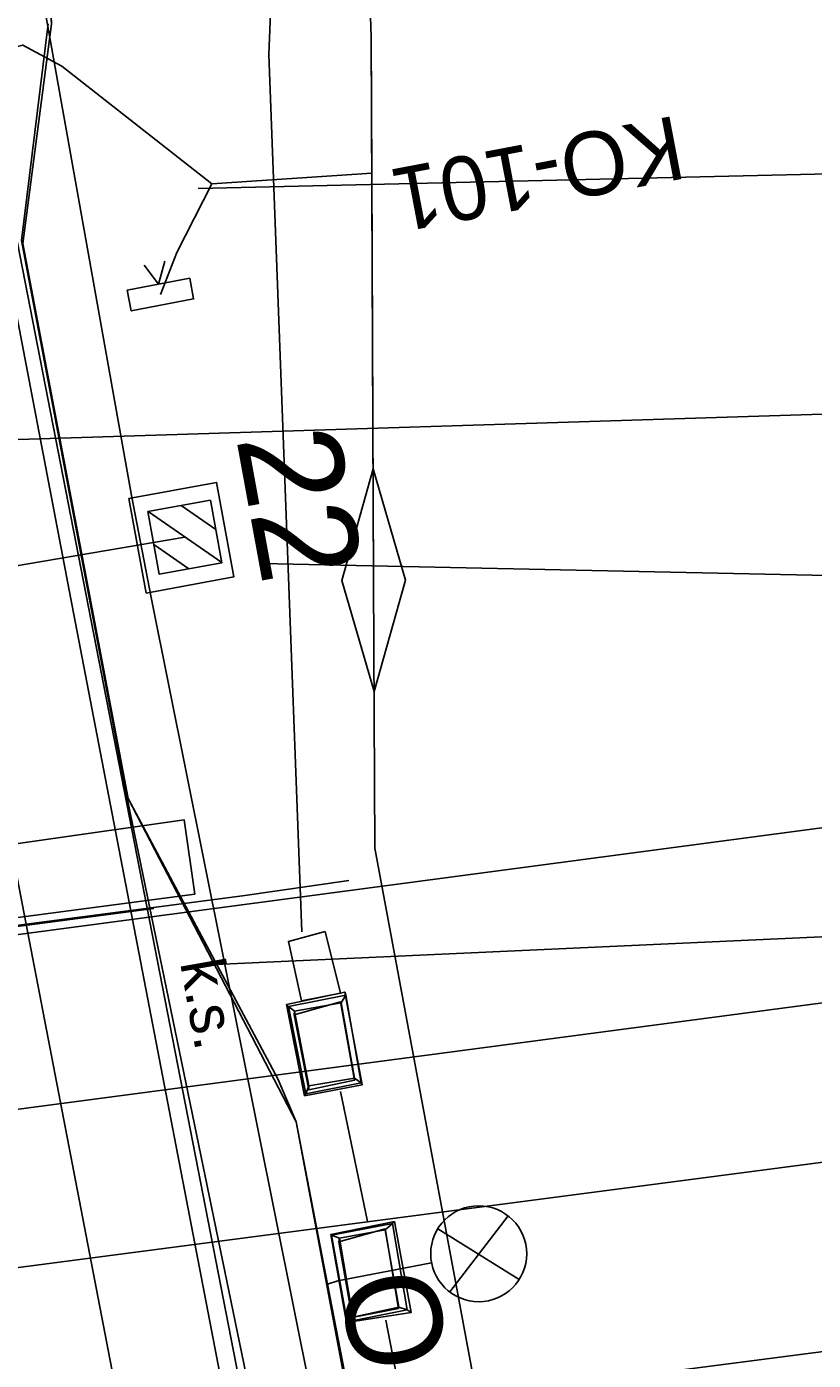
# Model space of a CAD drawing. Extents: x -545736 to -544888, y -1122892 to -1119128.
# Drawn here: x -545096.04 to -545083.68, y -1122320.45 to -1122299.49 of the extents above; entities that cross this region are included whole.
import ezdxf

# ---------------------------------------------------------------- set-up
doc = ezdxf.new("R2010")
doc.units = 0
for name, color, linetype in [('osvětlené plochy-hodnota-obrys', 7, 'Continuous'), ('Vrstva 1', 7, 'Continuous'), ('Vrstva 1 - Koleje', 7, 'Continuous'), ('Vrstva 11 - Trakce', 7, 'Continuous'), ('Vrstva 12 - Trakce zaklady', 7, 'Continuous'), ('Vrstva 17', 7, 'Continuous'), ('Vrstva 17_ploty - zabradli', 7, 'Continuous'), ('Vrstva 18', 7, 'Continuous'), ('Vrstva 25', 7, 'Continuous'), ('Vrstva 26', 7, 'Continuous'), ('Vrstva 27', 7, 'Continuous'), ('Vrstva 28 - zabzar', 7, 'Continuous'), ('Vrstva 31', 7, 'Continuous'), ('Vrstva 32', 7, 'Continuous'), ('Vrstva 36', 7, 'Continuous'), ('Vrstva 4 - Teren - stezky - prechody - plochy', 7, 'Continuous'), ('Vrstva 51', 7, 'Continuous'), ('Vrstva 63', 7, 'Continuous')]:
    doc.layers.add(name, color=color, linetype=linetype)

msp = doc.modelspace()

# ---------------------------------------------------------------- linework, layer by layer
at = {"layer": 'osvětlené plochy-hodnota-obrys'}
msp.add_lwpolyline([(-545104.447, -1122260.603), (-545047.997, -1122549.826)], dxfattribs=at)
at = {"layer": 'Vrstva 1'}
for points in [[(-545148.51, -1122325.585), (-545144.135, -1122325.279), (-545127.963, -1122323.132), (-545101.215, -1122319.654), (-545075.12, -1122316.237)], [(-545074.598, -1122319.154), (-545096.849, -1122322.043), (-545128.213, -1122326.198), (-545143.569, -1122328.203), (-545147.826, -1122328.702)]]:
    msp.add_lwpolyline(points, dxfattribs=at)
at = {"layer": 'Vrstva 1 - Koleje'}
msp.add_lwpolyline([(-545113.376, -1122218.519), (-545113.071, -1122220.278), (-545112.348, -1122224.453), (-545111.157, -1122231.266), (-545109.547, -1122240.396), (-545108.011, -1122249.024), (-545106.448, -1122257.717), (-545104.028, -1122271.035), (-545102.537, -1122279.147), (-545101.024, -1122287.292), (-545099.431, -1122295.796), (-545097.933, -1122303.72), (-545096.244, -1122312.592), (-545094.57, -1122321.295), (-545093.263, -1122328.028), (-545091.542, -1122336.847), (-545089.85, -1122345.509), (-545088.55, -1122352.199), (-545087.631, -1122356.921)], dxfattribs=at)
at = {"layer": 'Vrstva 11 - Trakce'}
for p, q in [((-545093.614, -1122307.016), (-545093.07, -1122307.391)), ((-545094.135, -1122307.112), (-545092.975, -1122307.913)), ((-545114.361, -1122311.03), (-545093.556, -1122307.514)), ((-545094.043, -1122307.631), (-545093.492, -1122308.011))]:
    msp.add_line(p, q, dxfattribs=at)
msp.add_lwpolyline([(-545093.154, -1122306.932), (-545092.974, -1122307.916), (-545093.958, -1122308.096), (-545094.138, -1122307.112)], close=True, dxfattribs=at)
at = {"layer": 'Vrstva 12 - Trakce zaklady'}
for p, q in [((-545094.436, -1122306.906), (-545093.059, -1122306.654)), ((-545092.787, -1122308.139), (-545094.164, -1122308.391))]:
    msp.add_line(p, q, dxfattribs=at)
for points in [[(-545094.164, -1122308.391), (-545094.436, -1122306.906), (-545093.059, -1122306.654), (-545092.787, -1122308.139), (-545094.164, -1122308.391)], [(-545093.059, -1122306.654), (-545093.059, -1122306.654), (-545092.787, -1122308.139), (-545092.787, -1122308.139)], [(-545094.436, -1122306.906), (-545094.436, -1122306.906), (-545094.164, -1122308.391), (-545094.164, -1122308.391)]]:
    msp.add_lwpolyline(points, dxfattribs=at)
at = {"layer": 'Vrstva 17'}
for p, q in [((-545090.684, -1122318.27), (-545091.11, -1122316.223)), ((-545090, -1122321.861), (-545090.398, -1122319.821))]:
    msp.add_line(p, q, dxfattribs=at)
for points in [[(-545091.717, -1122313.718), (-545092.238, -1122299.93), (-545089.495, -1122232.824), (-545090.394, -1122139.176), (-545080.236, -1122138.183), (-545080.486, -1122136.786), (-545077.607, -1122137.095), (-545077.582, -1122138.495)], [(-545150.29, -1122320.438), (-545144.887, -1122320.012), (-545115.504, -1122316.324), (-545074.789, -1122310.916)], [(-545074.698, -1122313.665), (-545111.863, -1122318.578), (-545144.692, -1122322.779), (-545149.67, -1122323.128)]]:
    msp.add_lwpolyline(points, dxfattribs=at)
msp.add_lwpolyline([(-545113.399, -1122315.705), (-545113.531, -1122314.631), (-545106.085, -1122313.699), (-545100.154, -1122312.892), (-545093.568, -1122311.954), (-545093.401, -1122313.123), (-545099.916, -1122313.983), (-545105.938, -1122314.779)], close=True, dxfattribs=at)
at = {"layer": 'Vrstva 17_ploty - zabradli'}
msp.add_line((-545111.225, -1122315.617), (-545094.046, -1122313.35), dxfattribs=at)
at = {"layer": 'Vrstva 18'}
for points in [[(-545145.417, -1122319.736), (-545144.484, -1122319.672), (-545119.425, -1122316.644), (-545117.758, -1122316.442), (-545092.653, -1122313.15), (-545090.978, -1122312.91)], [(-545091.043, -1122314.664), (-545091.024, -1122314.713), (-545091.099, -1122314.832), (-545091.112, -1122314.818)], [(-545091.958, -1122314.859), (-545091.929, -1122314.889), (-545091.833, -1122314.964), (-545091.838, -1122315.022)], [(-545090.771, -1122316.12), (-545090.787, -1122316.087), (-545090.888, -1122316.014), (-545090.889, -1122316.049)], [(-545091.677, -1122316.292), (-545091.657, -1122316.264), (-545091.606, -1122316.137), (-545091.608, -1122316.2)], [(-545090.264, -1122318.27), (-545090.295, -1122318.301), (-545090.409, -1122318.402), (-545090.408, -1122318.386)], [(-545091.264, -1122318.475), (-545091.251, -1122318.481), (-545091.126, -1122318.531), (-545091.138, -1122318.586)], [(-545090.002, -1122319.7), (-545090.063, -1122319.656), (-545090.195, -1122319.613), (-545090.199, -1122319.634)], [(-545091.016, -1122319.855), (-545091.004, -1122319.843), (-545090.917, -1122319.77), (-545090.927, -1122319.778)]]:
    msp.add_lwpolyline(points, dxfattribs=at)
for points in [[(-545091.677, -1122316.292), (-545090.771, -1122316.12), (-545091.043, -1122314.664), (-545091.958, -1122314.859)], [(-545091.657, -1122316.264), (-545090.787, -1122316.087), (-545091.024, -1122314.713), (-545091.929, -1122314.889)], [(-545091.838, -1122315.022), (-545091.608, -1122316.2), (-545090.889, -1122316.049), (-545091.112, -1122314.818)], [(-545091.606, -1122316.137), (-545090.888, -1122316.014), (-545091.099, -1122314.832), (-545091.833, -1122314.964)], [(-545091.016, -1122319.855), (-545090.002, -1122319.7), (-545090.264, -1122318.27), (-545091.264, -1122318.475)], [(-545091.004, -1122319.843), (-545090.063, -1122319.656), (-545090.295, -1122318.301), (-545091.251, -1122318.481)], [(-545090.927, -1122319.778), (-545090.199, -1122319.634), (-545090.408, -1122318.386), (-545091.138, -1122318.586)], [(-545090.917, -1122319.77), (-545090.195, -1122319.613), (-545090.409, -1122318.402), (-545091.126, -1122318.531)]]:
    msp.add_lwpolyline(points, close=True, dxfattribs=at)
at = {"layer": 'Vrstva 25'}
for p, q in [((-545088.477, -1122318.179), (-545089.394, -1122319.376)), ((-545088.301, -1122319.179), (-545089.583, -1122318.384)), ((-545089.679, -1122318.916), (-545091.152, -1122319.199))]:
    msp.add_line(p, q, dxfattribs=at)
msp.add_circle((-545088.938, -1122318.776), 0.754, dxfattribs=at)
at = {"layer": 'Vrstva 26'}
for points in [[(-545091.312, -1122319.256), (-545091.806, -1122316.702), (-545092.096, -1122316.024), (-545094.445, -1122311.621), (-545096.102, -1122302.896), (-545095.653, -1122299.445), (-545095.783, -1122296.662), (-545096.017, -1122293.637), (-545097.072, -1122285.85), (-545097.996, -1122280.011), (-545097.935, -1122279.662), (-545098.223, -1122276.93), (-545099.99, -1122270.495), (-545100.829, -1122263.058), (-545101.528, -1122261.609)], [(-545089.248, -1122329.984), (-545089.355, -1122329.595), (-545090.625, -1122323.213), (-545090.711, -1122322.359), (-545091.312, -1122319.256), (-545091.152, -1122319.199)]]:
    msp.add_lwpolyline(points, dxfattribs=at)
at = {"layer": 'Vrstva 27'}
msp.add_line((-545094.462, -1122303.633), (-545094.459, -1122303.629), dxfattribs=at)
msp.add_lwpolyline([(-545094.197, -1122303.24), (-545093.971, -1122303.536), (-545093.87, -1122303.178)], dxfattribs=at)
msp.add_lwpolyline([(-545094.462, -1122303.63), (-545093.48, -1122303.443), (-545093.418, -1122303.77), (-545094.4, -1122303.957)], close=True, dxfattribs=at)
at = {"layer": 'Vrstva 28 - zabzar'}
for points in [[(-545090.63, -1122299.65), (-545090.83, -1122293.64), (-545090.33, -1122285.9), (-545090.39, -1122281.43), (-545091.98, -1122278.11), (-545093.76, -1122273.59), (-545094.94, -1122269.52), (-545095.9, -1122261.38), (-545096.26, -1122251.32), (-545096.96, -1122243.55), (-545098.17, -1122239.69), (-545098.65, -1122230.66), (-545099.12, -1122222.68), (-545099.31, -1122222.23), (-545100.05, -1122215.99), (-545100.8, -1122212.68), (-545103.53, -1122204.35), (-545105.03, -1122196.24), (-545105.2, -1122196.04), (-545111.19, -1122191.9), (-545111.86, -1122183.52), (-545111.88, -1122183.3)], [(-545095.98, -1122406.73), (-545094.09, -1122406.23), (-545085.61, -1122404.88), (-545075.19, -1122403.13), (-545078.57, -1122384.82), (-545080.03, -1122378.7), (-545078.63, -1122376.44), (-545078.73, -1122374.54), (-545080.88, -1122364.73), (-545082.7, -1122354.07), (-545083.77, -1122348.32), (-545086.63, -1122333.57), (-545090.57, -1122312.4), (-545090.59, -1122308.19), (-545090.62, -1122301.79), (-545090.63, -1122299.65)], [(-545113.37, -1122303.04), (-545105.241, -1122302.038), (-545096.105, -1122299.779), (-545095.49, -1122300.11), (-545093.13, -1122301.96)], [(-545090.62, -1122301.79), (-545093.13, -1122301.96), (-545093.68, -1122303.04), (-545093.94, -1122303.7)]]:
    msp.add_lwpolyline(points, dxfattribs=at)
at = {"layer": 'Vrstva 31'}
for points in [[(-545099.42, -1122398.8), (-545103.547, -1122397.42), (-545105.43, -1122395.56), (-545106.274, -1122395.154), (-545105.78, -1122369.62), (-545105.743, -1122367.234), (-545104.85, -1122365.46), (-545104.4, -1122359.63), (-545103.057, -1122359.392), (-545086.529, -1122356.433), (-545084.91, -1122356.171), (-545085.349, -1122355.607), (-545086.586, -1122348.826), (-545087.046, -1122342.074), (-545091.806, -1122316.702), (-545094.445, -1122311.621), (-545096.102, -1122302.896), (-545095.653, -1122299.445), (-545096.017, -1122293.637), (-545097.072, -1122285.85), (-545097.996, -1122280.011), (-545097.935, -1122279.662)], [(-545095.98, -1122406.73), (-545094.09, -1122406.23), (-545085.61, -1122404.88), (-545075.19, -1122403.13), (-545078.57, -1122384.82), (-545080.03, -1122378.7), (-545078.63, -1122376.44), (-545078.73, -1122374.54), (-545080.88, -1122364.73), (-545082.7, -1122354.07), (-545083.77, -1122348.32), (-545086.63, -1122333.57), (-545090.57, -1122312.4), (-545090.59, -1122308.19), (-545090.62, -1122301.79), (-545090.63, -1122299.65), (-545090.83, -1122293.64)], [(-545095.703, -1122299.445), (-545096.126, -1122302.853), (-545094.453, -1122311.67), (-545086.005, -1122352.609), (-545085.399, -1122355.607), (-545085.45, -1122356.199), (-545086.529, -1122356.458), (-545103.057, -1122359.392), (-545104.4, -1122359.63), (-545104.414, -1122359.678), (-545104.871, -1122365.415), (-545105.715, -1122367.212), (-545105.802, -1122369.575), (-545106.034, -1122382.516), (-545106.23, -1122395.131), (-545105.43, -1122395.56), (-545103.547, -1122397.42), (-545100.71, -1122398.51), (-545099.42, -1122398.8), (-545099.54, -1122400.09), (-545099.24, -1122402.115), (-545098.313, -1122409.178)], [(-545090.598, -1122306.44), (-545090.09, -1122308.188), (-545090.582, -1122309.94), (-545091.09, -1122308.192), (-545090.598, -1122306.44)]]:
    msp.add_lwpolyline(points, dxfattribs=at)
at = {"layer": 'Vrstva 32'}
msp.add_lwpolyline([(-545075.19, -1122403.13), (-545078.57, -1122384.82), (-545080.03, -1122378.7), (-545078.63, -1122376.44), (-545078.73, -1122374.54), (-545080.88, -1122364.73), (-545082.7, -1122354.07), (-545083.77, -1122348.32), (-545086.63, -1122333.57), (-545090.57, -1122312.4), (-545090.59, -1122308.19), (-545090.63, -1122299.65), (-545090.83, -1122293.64)], dxfattribs=at)
msp.add_lwpolyline([(-545075.19, -1122403.13), (-545078.57, -1122384.82), (-545080.03, -1122378.7), (-545078.63, -1122376.44), (-545078.73, -1122374.54), (-545080.88, -1122364.73), (-545082.7, -1122354.07), (-545083.77, -1122348.32), (-545086.63, -1122333.57), (-545090.57, -1122312.4), (-545090.59, -1122308.19), (-545090.63, -1122299.65), (-545090.83, -1122293.64)], dxfattribs=at)
at = {"layer": 'Vrstva 36'}
msp.add_lwpolyline([(-545091.724, -1122314.8), (-545091.928, -1122313.867), (-545091.353, -1122313.713), (-545091.111, -1122314.681)], close=True, dxfattribs=at)
at = {"layer": 'Vrstva 4 - Teren - stezky - prechody - plochy'}
for points in [[(-545070.278, -1122429.488), (-545072.618, -1122417.894), (-545080.534, -1122377.233), (-545080.813, -1122375.639), (-545085.315, -1122351.9), (-545085.715, -1122350.161), (-545094.088, -1122308.462), (-545094.396, -1122306.861), (-545099.393, -1122278.86), (-545099.655, -1122277.461), (-545106.254, -1122241.136), (-545106.526, -1122239.499)], [(-545071.756, -1122430.223), (-545074.076, -1122418.135), (-545081.968, -1122377.565), (-545087.268, -1122350.478), (-545095.305, -1122308.703), (-545101.263, -1122277.511), (-545107.8, -1122241.308)]]:
    msp.add_lwpolyline(points, dxfattribs=at)
at = {"layer": 'Vrstva 51'}
for points in [[(-545074.789, -1122310.916), (-545115.504, -1122316.324), (-545144.887, -1122320.012), (-545150.29, -1122320.438)], [(-545149.67, -1122323.128), (-545144.692, -1122322.779), (-545111.863, -1122318.578), (-545074.698, -1122313.665)]]:
    msp.add_lwpolyline(points, dxfattribs=at)
at = {"layer": 'Vrstva 63'}
for p, q in [((-545060.71, -1122301.28), (-545093.345, -1122302.032)), ((-545060.013, -1122304.842), (-545116.818, -1122306.63)), ((-545059.271, -1122308.633), (-545092.346, -1122307.926)), ((-545058.484, -1122312.655), (-545093.075, -1122314.227))]:
    msp.add_line(p, q, dxfattribs=at)

# ---------------------------------------------------------------- texts
at = {"layer": 'Vrstva 11 - Trakce'}
msp.add_text('22', height=1.6, rotation=280.3795, dxfattribs=at).set_placement((-545092.751, -1122305.959))
at = {"layer": 'Vrstva 25'}
msp.add_text('OM26', height=1.5, rotation=280.9615, dxfattribs=at).set_placement((-545091.152, -1122319.199))
at = {"layer": 'Vrstva 27'}
msp.add_text('KO-101', height=1, rotation=190.7736, dxfattribs=at).set_placement((-545085.833, -1122300.882))
at = {"layer": 'Vrstva 63'}
msp.add_text('k.s.', height=0.6877, rotation=280.0577, dxfattribs=at).set_placement((-545093.633, -1122314.201))

doc.saveas('drawing.dxf')
